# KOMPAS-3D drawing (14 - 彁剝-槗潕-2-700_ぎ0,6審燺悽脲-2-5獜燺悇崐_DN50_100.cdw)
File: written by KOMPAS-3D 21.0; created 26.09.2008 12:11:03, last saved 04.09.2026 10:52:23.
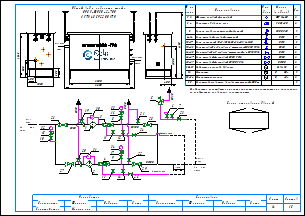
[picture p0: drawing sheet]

Sheets 1-2: A3, landscape

Document properties: Наименование: Макро:21; Автор: RaskoAdmin; Форматы листов документа: 2xA3; Полное имя файла: \\UR38nt01\Departments\КТО\КБ ПУРДГ\Заявки\Прайс-лист на типовые шкафы ГРПШ\ПРДГ_стандарт_20_03_2026\ПРДГ с РДНК\ПРДГ-ШУЭО-2-700_до0,6МПа_Рвых-2-5кПа_РДНК_DN50_100.cdw

Title block, sheet 1: Наименование: Пункт учета газа / ПУГ-Ш-400-Р / ЛГТИ.485922.001ТУ; designation: ЛГТИ.03.4411141; sheet number: 1; Количество листов документа: 2; organisation: ООО "ЭЛЬСТЕР Газэлектроника"; Форматы листов документа: A3; stored path: C:\Рабочие документы\Компас\ПУГ\Схема.cdw; Разработал: Устинов; Проверил: Кошкин; Утвердил: Кошкин
Title block, sheet 2: sheet number: 2; stored path: D:\Рабочие документы\Заявки\ПУРДГ\ПУРДГ-ШУЭО-2-100-Р 4411220.cdw; designation, second copy: ЛГТИ.03.4411141-

Views: Вид 1, Вид 2
Referenced files: wcvoit.frw
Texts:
  Normal
  Вход
  газа
  PDI
  Выход
  Р=     кПа
  DN100
  DN50
  DN20
  Импульс DN15
  ≥5DN
  HYSWLongFangSong
  № на
  схеме
  Усл.
  обозн.
  Марка
  (модель)
  Кол.
  Фильтр газовый фланцевый
  ФГ 16-50
  Регулятор давления газа
  РДНК-50
  Клапан предохранительный сбросной
  КПС DN20
  Кран шаровой газовый латунный
  DN15
  Кран кнопочный VE-РАСКО-НЗ-1,6-G1/2-М20
  Кран шаровой "под приварку" штуцерный DN20 PN16
  Кран шаровой "под приварку" штуцерный п/п DN15 PN16
  Кран шаровой фланцевый DN50 PN16
  Кран шаровой фланцевый DN100 PN16
  Индикатор перепада давления
  Delta 15
  Манометр
  Манометр-напоромер
  Электрообогреватель взрывозащищенный 400Вт
  0...     МПа
  0...     кПа
  Общий вид и габариты шкафа
  ПРДГ-ШУЭО-2-700
  Выход газа
  Вход газа
  Схема открывания дверей
  Р=        МПа
  logo-rasko-ge.png
  Предприятие изготовитель может заменять комплектующие на аналогичные,
  не ухудшающие заявленных характеристик.
  Должность
  Конструктор
  Фамилия
  Подпись
  Дата
  Согласовано
  Максимкин
  Лист
  Листов
  POLYLINE_STYLE_0.18_RGB_0_0_0
  POLYLINE_STYLE_0.50_RGB_0_0_0
  POLYLINE_STYLE_0.34_RGB_0_0_0
  PHANTOM_RGB_0_0_0_SC_1_THICK_0.18
  K5LT_THIN_RGB_0_0_0_THICK_0.18
  K5LT32769_RGB_0_0_0_THICK_0.18
  K5LT12_RGB_0_0_0_SC_1_THICK_0.18
  K5LT_DASHED_RGB_0_0_0_SC_1_THICK_0.18
  ACISOTGL_RGB_0_0_0_SC_0.8_THICK_0.25
  CONTINUOUS_RGB_0_127_31_THICK_0.3
  CONTINUOUS_RGB_0_0_255_THICK_0.35
  CONTINUOUS_RGB_255_0_0_THICK_0.35
  POLYLINE_STYLE_0.25_RGB_0_0_0
  CONTINUOUS_RGB_0_0_0_THICK_0.5
  POLYLINE_STYLE_0.35_RGB_0_0_255
  CONTINUOUS_RGB_0_0_0_THICK_0.4
  CONTINUOUS_RGB_0_0_0_THICK_0.35
  Без оформления
Dimensions and other numbers on the sheet: 1; 2; 3; 4; 5; 10; 27; 28; 29; 23; 8; 12; 19; 20; 21; 22; 25; 24; 30; 31; 15; 16; 26; 6; 7; 11; 14; 13; 33; 1, 2; 3, 4; 6-14; 9; 15-17; 18-23; 24-25; 26-27; 28-29; 30-31; 32; 33-34; 35; 400; 1050; 500; 305; 2300; 1565; 2600; 17; 34; 1000; 4130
